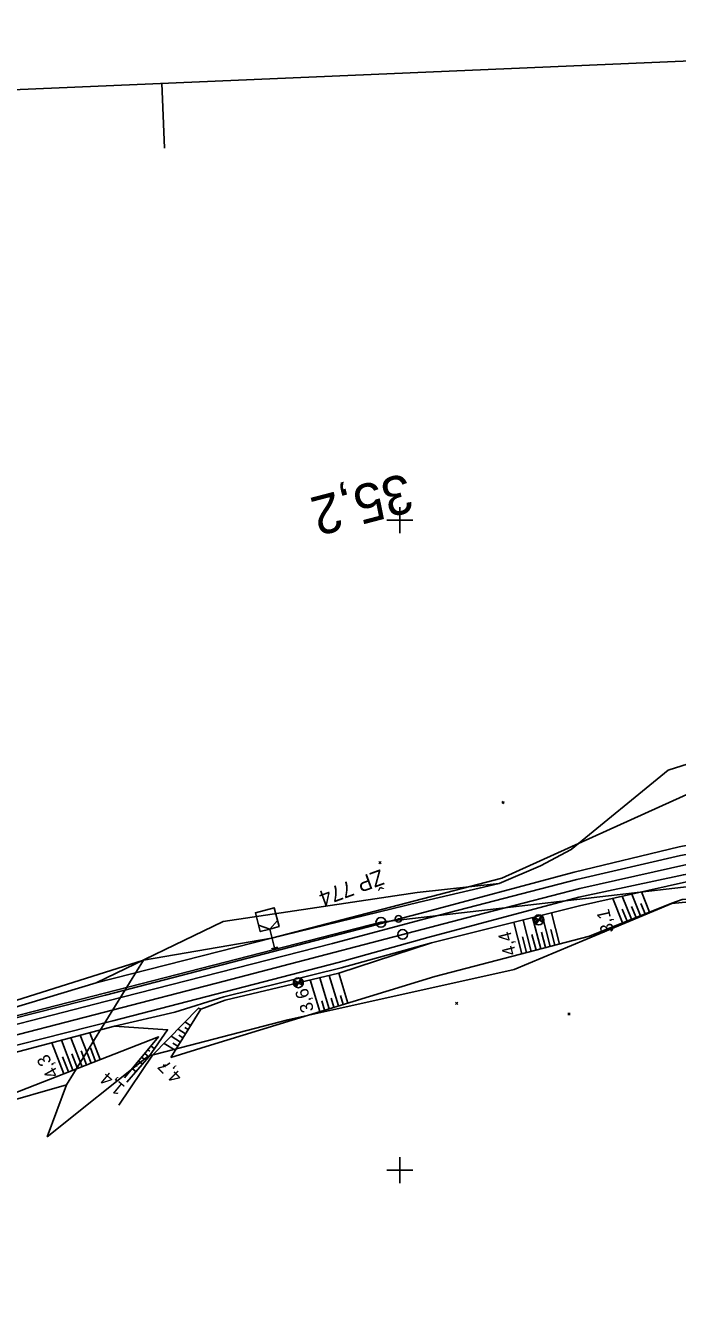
# Model space of a CAD drawing. Extents: x -806456 to -805395, y -1150847 to -1150506.
# Drawn here: x -806057.6 to -805957.2, y -1150719.3 to -1150523.9 of the extents above; entities that cross this region are included whole.
import ezdxf

# ---------------------------------------------------------------- set-up
doc = ezdxf.new("R2010")
doc.units = 0
for name, color, linetype in [('0381KM032-037P - Vrstva 1', 7, 'Continuous'), ('0381KM032-037P - Vrstva 4', 7, 'Continuous'), ('0381KM032-037P - Vrstva 48', 7, 'Continuous'), ('0381KM032-037P - Vrstva 49', 7, 'Continuous'), ('0381KM032-037P - Vrstva 55', 7, 'Continuous'), ('0381KM032-037P - Vrstva 7', 7, 'Continuous'), ('formát', 7, 'Continuous'), ('hran DP - hran DP', 7, 'Continuous'), ('krizky_1000 - Vrstva 1', 7, 'Continuous'), ('vyt_sit - polygon', 7, 'Continuous'), ('vyt_sit - stávající', 7, 'Continuous')]:
    doc.layers.add(name, color=color, linetype=linetype)

msp = doc.modelspace()

# ---------------------------------------------------------------- linework, layer by layer
at = {"layer": '0381KM032-037P - Vrstva 1'}
for points in [[(-805955.36, -1150652.84), (-805972.27, -1150656.66), (-805989.76, -1150661.17)], [(-805989.76, -1150661.17), (-806027.03, -1150670.9), (-806064.32, -1150680.56), (-806101.67, -1150690.24), (-806138.44, -1150699.75), (-806158.28, -1150704.94), (-806163.64, -1150706.34), (-806175.38, -1150709.4), (-806186.46, -1150712.29), (-806205.2, -1150717.19), (-806213.26, -1150719.29)]]:
    msp.add_lwpolyline(points, dxfattribs=at)
at = {"layer": '0381KM032-037P - Vrstva 4'}
for points in [[(-805920.59, -1150645.08), (-805938.49, -1150646.69), (-805957, -1150650.24), (-805973.18, -1150654.13), (-805996.94, -1150660.52), (-806010.57, -1150664.04), (-806045.29, -1150673.07), (-806070.44, -1150679.45), (-806076.44, -1150680.94), (-806080.95, -1150682.04), (-806094.16, -1150685.34), (-806107.83, -1150689.09)], [(-805923.83, -1150646.61), (-805939.39, -1150648.49), (-805956.78, -1150651.56), (-805972.77, -1150655.27), (-805996.74, -1150661.47), (-806010.38, -1150665.11), (-806045.15, -1150673.98), (-806070.28, -1150680.43), (-806094.02, -1150686.67), (-806107.78, -1150690.05)], [(-805923.37, -1150650.9), (-805938.15, -1150652.42), (-805956.35, -1150655.74), (-805972.37, -1150659.35), (-805995.12, -1150665.03), (-806009.04, -1150668.86), (-806027.1, -1150673.31), (-806034.62, -1150675.7), (-806043.91, -1150677.85), (-806068.97, -1150684.48)], [(-805923.42, -1150649.97), (-805938.4, -1150651.47), (-805956.35, -1150654.55), (-805972.44, -1150657.98), (-805995.68, -1150664.21)], [(-805995.68, -1150664.21), (-806009.49, -1150668.04), (-806044.17, -1150677), (-806069.3, -1150683.37)]]:
    msp.add_lwpolyline(points, dxfattribs=at)
at = {"layer": '0381KM032-037P - Vrstva 48'}
for p, q in [((-805962.94, -1150660.84), (-805964.27, -1150657.52)), ((-805961.55, -1150660.28), (-805962.79, -1150657.19)), ((-805965.72, -1150661.96), (-805967.24, -1150658.19)), ((-805964.33, -1150661.4), (-805965.76, -1150657.86)), ((-805963.64, -1150661.12), (-805964.33, -1150659.41)), ((-805962.24, -1150660.56), (-805962.89, -1150658.96)), ((-805978.31, -1150665.95), (-805979.56, -1150661.14)), ((-805976.86, -1150665.57), (-805978.1, -1150660.78)), ((-805975.4, -1150665.2), (-805976.65, -1150660.41)), ((-805965.03, -1150661.68), (-805965.76, -1150659.85)), ((-805981.21, -1150666.7), (-805982.47, -1150661.87)), ((-805979.76, -1150666.33), (-805981.01, -1150661.51)), ((-805977.58, -1150665.76), (-805978.21, -1150663.36)), ((-805976.13, -1150665.38), (-805976.75, -1150662.99)), ((-805980.48, -1150666.52), (-805981.11, -1150664.1)), ((-805979.03, -1150666.14), (-805979.66, -1150663.73)), ((-806012.31, -1150675.59), (-806013.79, -1150670.73)), ((-806010.87, -1150675.15), (-806012.33, -1150670.38)), ((-806009.44, -1150674.72), (-806010.87, -1150670.03)), ((-806008, -1150674.28), (-806009.41, -1150669.68)), ((-806008.72, -1150674.5), (-806009.14, -1150673.1)), ((-806011.59, -1150675.37), (-806012.03, -1150673.93)), ((-806010.15, -1150674.93), (-806010.59, -1150673.52)), ((-806046.12, -1150682.99), (-806047.73, -1150678.86)), ((-806032.99, -1150679.01), (-806034.14, -1150678.29)), ((-806032.59, -1150678.37), (-806033.1, -1150678.06)), ((-806032.2, -1150677.73), (-806033.07, -1150677.19)), ((-806051.71, -1150685.17), (-806053.56, -1150680.4)), ((-806050.31, -1150684.62), (-806052.1, -1150680.01)), ((-806048.91, -1150684.08), (-806050.65, -1150679.63)), ((-806047.52, -1150683.53), (-806049.19, -1150679.24)), ((-806038.31, -1150680.89), (-806037.77, -1150681.34)), ((-806034.58, -1150681.55), (-806036.29, -1150680.49)), ((-806033.78, -1150680.28), (-806035.21, -1150679.39)), ((-806034.18, -1150680.92), (-806034.96, -1150680.43)), ((-806033.39, -1150679.64), (-806034.03, -1150679.24)), ((-806051.01, -1150684.89), (-806051.92, -1150682.55)), ((-806049.61, -1150684.35), (-806050.49, -1150682.09)), ((-806048.21, -1150683.81), (-806049.07, -1150681.62)), ((-806046.82, -1150683.26), (-806047.64, -1150681.16)), ((-806039.75, -1150682.62), (-806039.43, -1150682.88)), ((-806039.27, -1150682.04), (-806038.62, -1150682.58)), ((-806038.79, -1150681.47), (-806038.49, -1150681.71)), ((-806041.19, -1150684.34), (-806040.59, -1150684.84)), ((-806040.71, -1150683.77), (-806040.41, -1150684.02)), ((-806040.23, -1150683.19), (-806039.61, -1150683.71))]:
    msp.add_line(p, q, dxfattribs=at)
at = {"layer": '0381KM032-037P - Vrstva 49'}
for p, q in [((-805984.28, -1150643.25), (-805983.92, -1150643.6)), ((-805983.92, -1150643.25), (-805984.27, -1150643.6)), ((-806002.88, -1150652.52), (-806003.24, -1150652.88)), ((-806003.24, -1150652.52), (-806002.88, -1150652.88)), ((-805991.06, -1150674.14), (-805991.41, -1150674.5)), ((-805991.41, -1150674.14), (-805991.06, -1150674.5)), ((-805973.79, -1150675.81), (-805974.14, -1150676.16)), ((-805974.14, -1150675.81), (-805973.79, -1150676.16)), ((-806036.06, -1150683.77), (-806036.41, -1150684.12)), ((-806036.41, -1150683.77), (-806036.06, -1150684.12))]:
    msp.add_line(p, q, dxfattribs=at)
for points in [[(-805973.62, -1150650.67), (-805958.72, -1150638.45), (-805944.76, -1150634.02), (-805913.4, -1150627.48)], [(-806076.44, -1150680.94), (-806070.44, -1150679.45), (-806045.29, -1150673.07), (-806010.57, -1150664.04), (-805996.94, -1150660.52), (-805973.18, -1150654.13), (-805957, -1150650.24), (-805938.49, -1150646.69)], [(-805973.62, -1150650.67), (-805978.37, -1150653.15), (-805984.72, -1150655.91), (-805997.34, -1150657.28), (-806027.21, -1150661.72), (-806046.76, -1150671.15)], [(-805923.37, -1150650.9), (-805938.15, -1150652.42), (-805956.35, -1150655.74), (-805972.37, -1150659.35), (-805995.12, -1150665.03)], [(-805923.15, -1150654.86), (-805936.98, -1150655.81), (-805944.5, -1150657.57), (-805956.52, -1150658.37), (-805958.13, -1150658.91), (-805970.8, -1150664), (-805994.63, -1150670.19)], [(-805984.72, -1150655.91), (-805997.04, -1150658.76), (-806019.75, -1150664.3), (-806046.76, -1150671.15)], [(-805995.12, -1150665.03), (-806009.04, -1150668.86), (-806027.1, -1150673.31), (-806034.62, -1150675.7), (-806043.91, -1150677.85), (-806068.97, -1150684.48)], [(-805995.12, -1150665.03), (-806009.41, -1150669.68), (-806026.88, -1150673.84), (-806030.63, -1150675.21), (-806035.27, -1150682.66)], [(-806046.76, -1150671.15), (-806070.76, -1150678.42)], [(-806035.27, -1150682.66), (-806029.14, -1150680.74), (-805994.63, -1150670.19)], [(-806043.26, -1150689.98), (-806038.08, -1150682.32), (-806030.99, -1150675.07), (-806030.63, -1150675.21)], [(-806042.01, -1150686.47), (-806038.62, -1150682.58), (-806035.75, -1150678.39), (-806043.91, -1150677.85)], [(-806042.38, -1150685.77), (-806037.14, -1150679.5), (-806067.5, -1150691.31), (-806072.52, -1150696.14), (-806083.69, -1150697.11)]]:
    msp.add_lwpolyline(points, dxfattribs=at)
at = {"layer": '0381KM032-037P - Vrstva 55'}
msp.add_line((-806039.45, -1150667.69), (-806051.33, -1150686.88), dxfattribs=at)
at = {"layer": '0381KM032-037P - Vrstva 7'}
for p, q in [((-806000.26, -1150661.33), (-806000.16, -1150661.33)), ((-806020.03, -1150662.91), (-806019.27, -1150665.81)), ((-806019.76, -1150665.94), (-806018.79, -1150665.69))]:
    msp.add_line(p, q, dxfattribs=at)
for points in [[(-806020.03, -1150662.91), (-806018.58, -1150662.53), (-806019.34, -1150659.63), (-806022.24, -1150660.39), (-806021.48, -1150663.29), (-806020.03, -1150662.91)], [(-806021.74, -1150662.32), (-806020.03, -1150662.91), (-806018.83, -1150661.56)]]:
    msp.add_lwpolyline(points, dxfattribs=at)
for centre, radius in [((-806000.21, -1150661.33), 0.5), ((-805999.58, -1150663.73), 0.75)]:
    msp.add_circle(centre, radius, dxfattribs=at)
at = {"layer": 'formát'}
for p, q in [((-805826.83, -1150523.88), (-806456.26, -1150550.6)), ((-806036.64, -1150532.78), (-806036.21, -1150542.77))]:
    msp.add_line(p, q, dxfattribs=at)
at = {"layer": 'hran DP - hran DP'}
for p, q in [((-805984.31, -1150655.05), (-805954.21, -1150641.47)), ((-806019.74, -1150664.32), (-805984.31, -1150655.05)), ((-805958.14, -1150658.97), (-805982.42, -1150669.1)), ((-805944.43, -1150657.58), (-805958.14, -1150658.97)), ((-806039.45, -1150667.69), (-806019.74, -1150664.32)), ((-806073.91, -1150678.57), (-806039.45, -1150667.69)), ((-805982.42, -1150669.1), (-806017.22, -1150676.88)), ((-806017.22, -1150676.88), (-806038.72, -1150682.46)), ((-806038.72, -1150682.46), (-806054.27, -1150694.84)), ((-806051.33, -1150686.88), (-806067.49, -1150691.49)), ((-806054.27, -1150694.84), (-806051.33, -1150686.88))]:
    msp.add_line(p, q, dxfattribs=at)
at = {"layer": 'krizky_1000 - Vrstva 1'}
for points in [[(-806000, -1150598), (-806000, -1150602)], [(-806002, -1150600), (-805998, -1150600)], [(-806000, -1150698), (-806000, -1150702)], [(-806002, -1150700), (-805998, -1150700)]]:
    msp.add_lwpolyline(points, dxfattribs=at)
at = {"layer": 'vyt_sit - polygon'}
for p, q in [((-806002.92, -1150661.86), (-805901.58, -1150650.08)), ((-806134.24, -1150695.52), (-806002.92, -1150661.86))]:
    msp.add_line(p, q, dxfattribs=at)
at = {"layer": 'vyt_sit - stávající'}
for p, q in [((-805979.05, -1150661.23), (-805979.34, -1150661.72)), ((-805979.28, -1150661.1), (-805978.61, -1150661.49)), ((-805978.79, -1150661.38), (-805979.17, -1150662.01)), ((-805978.61, -1150661.49), (-805978.22, -1150660.83)), ((-805978.07, -1150660.95), (-805978.44, -1150661.58)), ((-805977.89, -1150661.24), (-805978.19, -1150661.74)), ((-806002.97, -1150661.86), (-806002.87, -1150661.86)), ((-805978.61, -1150661.49), (-805979, -1150662.15)), ((-805977.96, -1150661.87), (-805978.61, -1150661.49)), ((-806016.06, -1150670.9), (-806016.35, -1150671.39)), ((-806016.29, -1150670.77), (-806015.62, -1150671.16)), ((-806015.8, -1150671.06), (-806016.17, -1150671.69)), ((-806015.62, -1150671.16), (-806016.01, -1150671.82)), ((-806015.62, -1150671.16), (-806015.24, -1150670.5)), ((-806014.97, -1150671.54), (-806015.62, -1150671.16)), ((-806015.08, -1150670.62), (-806015.45, -1150671.26)), ((-806014.9, -1150670.91), (-806015.2, -1150671.41))]:
    msp.add_line(p, q, dxfattribs=at)
for centre, radius in [((-806002.92, -1150661.86), 0.756), ((-805978.61, -1150661.49), 0.764), ((-806015.62, -1150671.16), 0.764)]:
    msp.add_circle(centre, radius, dxfattribs=at)
for centre, radius, start, end in [((-805978.61, -1150661.49), 0.765, 149.6712, 239.5647), ((-805978.61, -1150661.49), 0.764, 328.9824, 59.3004), ((-806015.62, -1150671.16), 0.765, 149.8433, 239.7368), ((-806015.62, -1150671.16), 0.764, 329.1545, 59.4725)]:
    msp.add_arc(centre, radius, start, end, dxfattribs=at)

# ---------------------------------------------------------------- texts
at = {"layer": '0381KM032-037P - Vrstva 48'}
for s, rotation, p in [('3,1', 102.684, (-805967.01, -1150663.31)), ('4,4', 104.5589, (-805982.06, -1150666.72)), ('3,6', 106.9987, (-806013.19, -1150675.4)), ('4,3', 119.1846, (-806052.44, -1150685.23)), ('4,7', 134.6698, (-806033.39, -1150685.47)), ('1,4', 140.1468, (-806042.18, -1150687.14))]:
    msp.add_text(s, height=2, rotation=rotation, dxfattribs=at).set_placement(p)
at = {"layer": '0381KM032-037P - Vrstva 7'}
msp.add_text('35,2', height=6, rotation=194.6315, dxfattribs=at).set_placement((-805999, -1150592.71))
at = {"layer": 'vyt_sit - stávající'}
msp.add_text('ŽP 774', height=2.4, rotation=200, dxfattribs=at).set_placement((-806002.96, -1150653.66))

doc.saveas('drawing.dxf')
